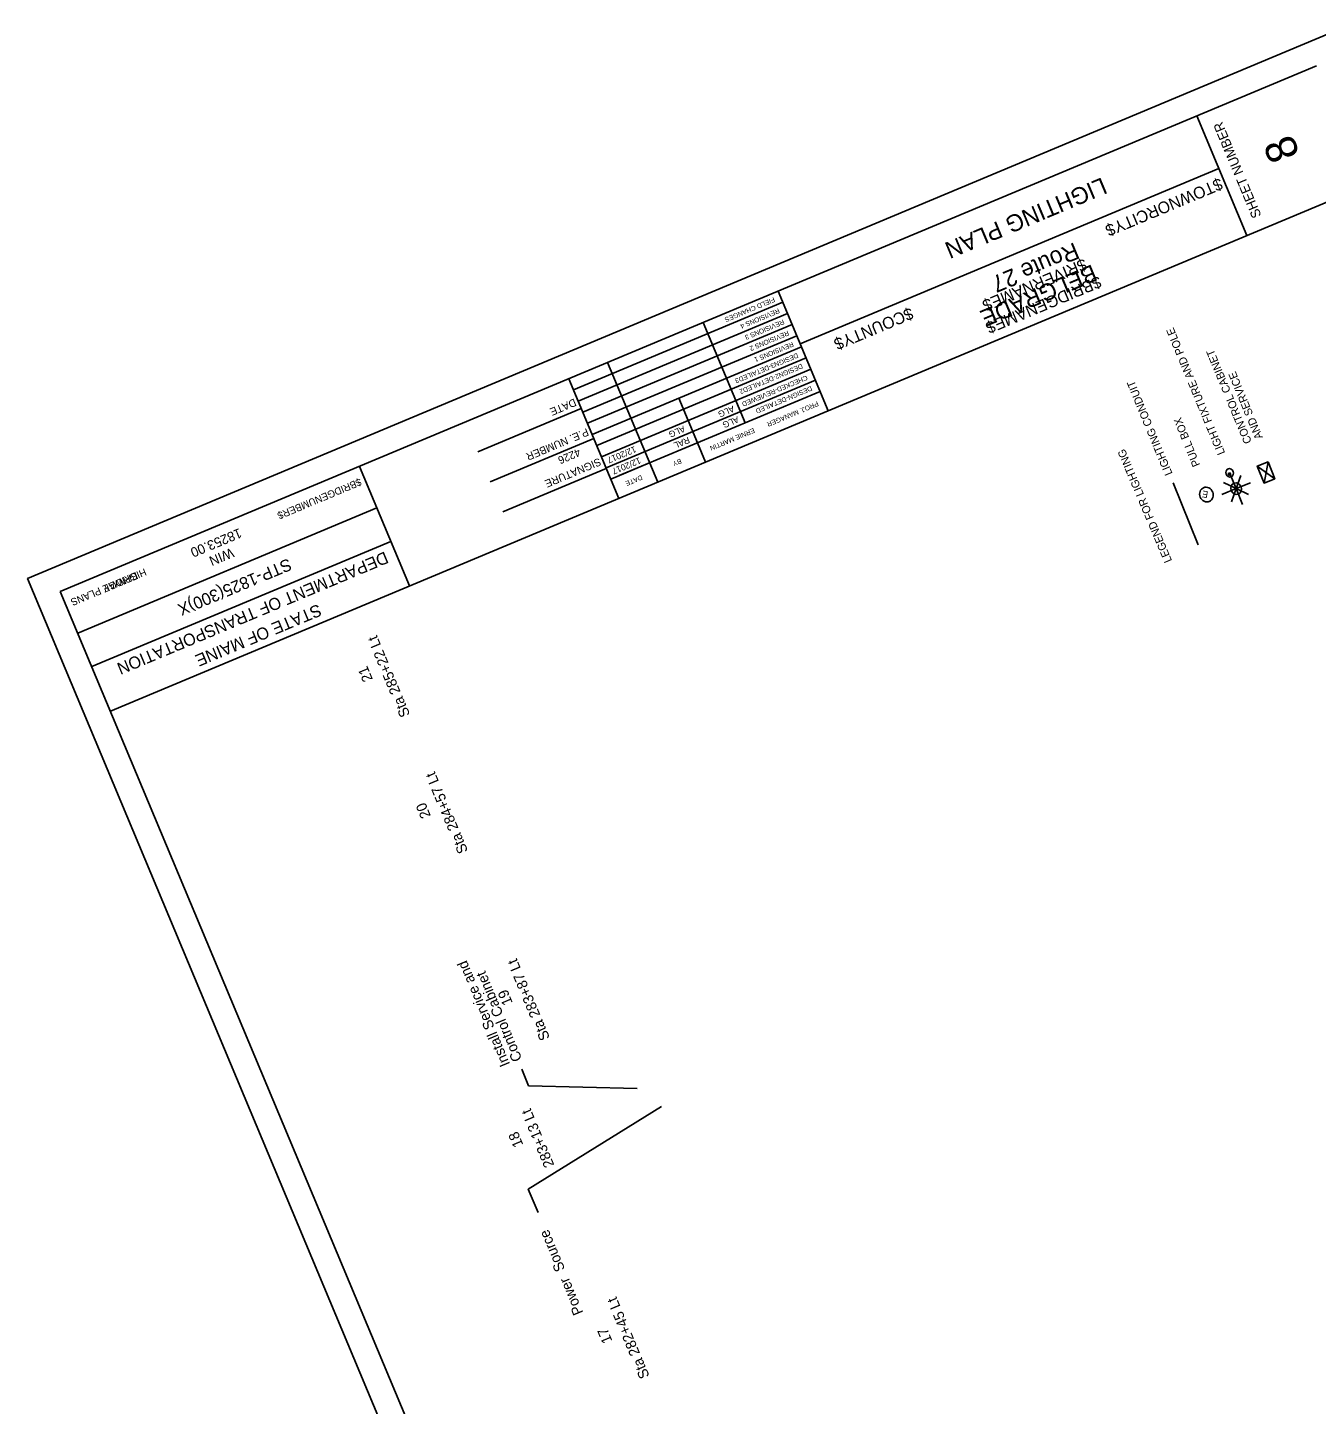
# Model space of a CAD drawing. Extents: x 1111244 to 1112080, y 617020 to 618016.
# Drawn here: x 1111244 to 1111741, y 617485 to 618016 of the extents above; entities that cross this region are included whole.
import ezdxf

# ---------------------------------------------------------------- set-up
doc = ezdxf.new("R2010")
doc.units = 0
for name, color, linetype in [('ANNOTATION', 7, 'Continuous'), ('BORDER', 7, 'Continuous'), ('BRIDGE_TITLE', 7, 'Continuous'), ('D_Lighting', 7, 'Continuous'), ('D_Lighting_Text', 7, 'Continuous'), ('Default', 7, 'Continuous'), ('HIGHWAY_TITLE', 7, 'Continuous'), ('Liting Text', 7, 'Continuous'), ('PLOT BOUNDARY', 7, 'Continuous'), ('Prp Liting', 7, 'Continuous'), ('UTILS GRND', 7, 'Continuous'), ('VSL-LUMINAIRES', 7, 'Continuous')]:
    doc.layers.add(name, color=color, linetype=linetype)

msp = doc.modelspace()

# ---------------------------------------------------------------- linework, layer by layer
at = {"layer": 'BORDER'}
for p, q in [((1111741.33, 618001.36), (1111257.06, 617798.62)), ((1111714.52, 617935.93), (1111695.21, 617982.05)), ((1111703.73, 617961.72), (1111542.3, 617894.14)), ((1111760.64, 617955.24), (1111276.37, 617752.5)), ((1111553.1, 617868.35), (1111533.79, 617914.47)), ((1111472.38, 617834.56), (1111453.08, 617880.68)), ((1111457.9, 617869.15), (1111418.02, 617852.46)), ((1111462.73, 617857.62), (1111422.85, 617840.92)), ((1111391.71, 617800.79), (1111372.4, 617846.91)), ((1111467.56, 617846.09), (1111427.67, 617829.39)), ((1111379.1, 617830.87), (1111263.8, 617782.6)), ((1111384.5, 617817.98), (1111269.2, 617769.71)), ((1111257.07, 617798.63), (1111566.01, 617060.69))]:
    msp.add_line(p, q, dxfattribs=at)
for points in [[(1111535.57, 617910.17), (1111454.87, 617876.39)], [(1111537.37, 617905.88), (1111456.67, 617872.09)], [(1111521.15, 617863.73), (1111504.96, 617902.4)], [(1111539.17, 617901.58), (1111458.47, 617867.8)], [(1111540.97, 617897.28), (1111460.27, 617863.5)], [(1111542.77, 617892.99), (1111462.07, 617859.2)], [(1111544.57, 617888.69), (1111463.87, 617854.9)], [(1111487.37, 617840.84), (1111468.07, 617886.96)], [(1111465.67, 617850.61), (1111546.37, 617884.39)], [(1111548.16, 617880.09), (1111467.47, 617846.31)], [(1111549.96, 617875.8), (1111472.52, 617843.38)], [(1111502.7, 617856.01), (1111495.51, 617873.2)], [(1111505.82, 617848.56), (1111502.7, 617856.01)], [(1111484.26, 617848.28), (1111469.27, 617842.01)]]:
    msp.add_lwpolyline(points, dxfattribs=at)
at = {"layer": 'D_Lighting'}
for p, q in [((1111707.87, 617844.41), (1111710.38, 617838.31)), ((1111725.28, 617842.1), (1111718.54, 617847.03)), ((1111722.69, 617848.67), (1111721.14, 617840.46)), ((1111710.38, 617838.31), (1111704.89, 617836.05)), ((1111710.38, 617838.31), (1111705.56, 617840.62)), ((1111710.38, 617838.31), (1111708.59, 617833.27)), ((1111710.38, 617838.31), (1111712.17, 617843.35)), ((1111710.38, 617838.31), (1111715.86, 617840.58)), ((1111710.38, 617838.31), (1111712.89, 617832.22)), ((1111710.38, 617838.31), (1111715.2, 617836))]:
    msp.add_line(p, q, dxfattribs=at)
msp.add_lwpolyline([(1111722.69, 617848.67), (1111725.28, 617842.1), (1111721.14, 617840.46), (1111718.54, 617847.03)], close=True, dxfattribs=at)
for centre, major_axis in [((1111707.88, 617844.41), (-0.62, 1.52)), ((1111710.38, 617838.31), (-0.85, 2.08))]:
    msp.add_ellipse(centre, major_axis=major_axis, ratio=0.899857, dxfattribs=at)
at = {"layer": 'D_Lighting_Text'}
for points in [[(1111434.96, 617614.51), (1111437.62, 617608.16), (1111479.52, 617607.02)], [(1111441.27, 617559.26), (1111437.5, 617568.26), (1111488.8, 617600.07)]]:
    msp.add_lwpolyline(points, dxfattribs=at)
at = {"layer": 'Default'}
msp.add_lwpolyline([(1111572.69, 617019.61), (1111244.44, 617803.67), (1111751.77, 618016.07), (1112080.02, 617232.01)], close=True, dxfattribs=at)
at = {"layer": 'PLOT BOUNDARY'}
msp.add_lwpolyline([(1112080.02, 617232.01), (1111751.77, 618016.07), (1111244.44, 617803.67), (1111572.69, 617019.61)], close=True, dxfattribs=at)
at = {"layer": 'Prp Liting'}
msp.add_line((1111695.77, 617816.68), (1111686.09, 617840.6), dxfattribs=at)
at = {"layer": 'UTILS GRND'}
msp.add_ellipse((1111698.94, 617836.02), major_axis=(1.1, -2.66), ratio=0.901044, dxfattribs=at)
at = {"layer": 'VSL-LUMINAIRES'}
msp.add_lwpolyline([(1111707.97, 617844.44), (1111707.31, 617844.15), (1111707.63, 617843.46), (1111708.29, 617843.75)], close=True, dxfattribs=at)
msp.add_lwpolyline([(1111707.97, 617844.44), (1111707.31, 617844.15), (1111707.63, 617843.46), (1111708.29, 617843.75)], close=True, dxfattribs=at)
msp.add_lwpolyline([(1111707.87, 617844.41), (1111707.87, 617844.41)], dxfattribs=at)

# ---------------------------------------------------------------- texts
at = {"layer": 'ANNOTATION'}
msp.add_text('4226', height=3, rotation=202.7167, dxfattribs=at).set_placement((1111456.85, 617853.87))
at = {"layer": 'BORDER'}
for s, height, rotation, p in [('SHEET NUMBER', 3.7264, 112.7167, (1111720.2, 617943.54)), ('8', 12.1, 112.7167, (1111735.13, 617967.25)), ('LIGHTING PLAN', 6.5214, 202.7167, (1111658.72, 617958.45)), ('FIELD CHANGES', 1.8637, 202.7167, (1111532.11, 617912.16)), ('REVISIONS 4', 1.8637, 202.7167, (1111533.91, 617907.86)), ('REVISIONS 3', 1.8637, 202.7167, (1111535.71, 617903.57)), ('REVISIONS 2', 1.8637, 202.7167, (1111537.51, 617899.27)), ('REVISIONS 1', 1.8637, 202.7167, (1111539.31, 617894.97)), ('DESIGN3-DETAILED3', 1.8637, 202.7167, (1111541.11, 617890.67)), ('DESIGN2-DETAILED2', 1.8637, 202.7167, (1111542.83, 617886.55)), ('CHECKED-REVIEWED', 1.8637, 202.7167, (1111544.7, 617882.08)), ('DESIGN-DETAILED', 1.8637, 202.7167, (1111546.43, 617877.96)), ('DATE', 2.953, 202.7167, (1111455.2, 617873.12)), ('ALG', 2.423, 202.7167, (1111516.34, 617870.4)), ('PROJ. MANAGER', 1.8637, 202.7167, (1111548.91, 617872.04)), ('ALG', 2.423, 202.7167, (1111518.06, 617866.28)), ('P.E. NUMBER', 2.9528, 202.7167, (1111459.99, 617861.68)), ('ALG', 2.423, 202.7167, (1111497.3, 617862.63)), ('ERNIE MARTIN', 1.8637, 202.7167, (1111524.31, 617861.74)), ('12/2017', 2.423, 202.7167, (1111478.47, 617854.75)), ('RAL', 2.423, 202.7167, (1111499.1, 617858.34)), ('SIGNATURE', 2.953, 202.7167, (1111464.78, 617850.24)), ('12/2017', 2.423, 202.7167, (1111480.27, 617850.45)), ('BY', 1.857, 202.7167, (1111496.11, 617849.94)), ('DATE', 1.857, 202.7167, (1111481.03, 617843.62)), ('18253.00', 3.726, 202.7167, (1111326.06, 617823.15)), ('DEPARTMENT OF TRANSPORTATION', 4.6588, 202.7167, (1111382.24, 617814.2)), ('WIN', 3.726, 202.7167, (1111322.99, 617815.58)), ('STP-1825(300)X', 4.6588, 202.7167, (1111345.04, 617811.56)), ('STATE OF MAINE', 4.6588, 202.7167, (1111356.54, 617793.95))]:
    msp.add_text(s, height=height, rotation=rotation, dxfattribs=at).set_placement(p)
at = {"layer": 'BRIDGE_TITLE'}
for s, height, p in [('$TOWNORCITY$', 4.5358, (1111704, 617958.2)), ('$RIVERNAME$', 4.5358, (1111651.61, 617927.17)), ('$BRIDGENAME$', 4.5358, (1111657.22, 617920.43)), ('$COUNTY$', 4.536, (1111584.74, 617908.27)), ('$BRIDGENUMBER$', 2.795, (1111372.48, 617842.38)), ('BRIDGE PLANS', 2.795, (1111286.26, 617806.28))]:
    msp.add_text(s, height=height, rotation=202.7167, dxfattribs=at).set_placement(p)
at = {"layer": 'D_Lighting_Text'}
for s, p in [('Sta 285+22 Lt', (1111392, 617751.18)), ('21', (1111377.63, 617764.79)), ('Sta 284+57 Lt', (1111414.32, 617698.62)), ('20', (1111399.98, 617712.16)), ('Install Service and', (1111430.53, 617616.45)), ('Control Cabinet', (1111435.19, 617618.4)), ('Sta 283+87 Lt', (1111445.89, 617626.58)), ('19', (1111431.55, 617640.12)), ('283+13 Lt', (1111447.58, 617577.56)), ('18', (1111435.64, 617585.36)), ('Power  Source', (1111458.74, 617520.68)), ('Sta 282+45 Lt', (1111484.31, 617496.2)), ('17', (1111469.97, 617509.75))]:
    msp.add_text(s, height=4, rotation=112.7167, dxfattribs=at).set_placement(p)
at = {"layer": 'HIGHWAY_TITLE'}
for s, height, p in [('Route 27', 6.521, (1111648.07, 617933.37)), ('BELGRADE', 6.521, (1111654.88, 617924.9)), ('HIGHWAY PLANS', 2.795, (1111289.53, 617807.65))]:
    msp.add_text(s, height=height, rotation=202.7167, dxfattribs=at).set_placement(p)
at = {"layer": 'Liting Text'}
for s, height, rotation, p in [('LIGHT FIXTURE AND POLE', 3.0627, 112.3917, (1111706.19, 617852.07)), ('CONTROL CABINET ', 3.0627, 112.4703, (1111716.47, 617856.36)), ('AND SERVICE', 3.0627, 112.4703, (1111720.72, 617858.11)), ('LIGHTING CONDUIT', 3.0627, 112.3917, (1111685.9, 617844.12)), ('PULL BOX', 3.063, 112.0392, (1111696.59, 617847.48)), ('LEGEND FOR LIGHTING', 3.0627, 112.9239, (1111685.71, 617810.53))]:
    msp.add_text(s, height=height, rotation=rotation, dxfattribs=at).set_placement(p)
at = {"layer": 'UTILS GRND'}
msp.add_text('E', height=2.58, rotation=169.6801, dxfattribs=at).set_placement((1111699.75, 617837.19))

doc.saveas('drawing.dxf')
